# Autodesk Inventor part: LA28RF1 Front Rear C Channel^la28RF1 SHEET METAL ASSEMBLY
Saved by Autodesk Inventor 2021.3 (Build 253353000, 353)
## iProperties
Created: 2023-01
Part Number: LA28RF1 Front Rear C Channel^la28RF1 SHEET METAL ASSEMBLY
Material: Generic
Document SubType Name: Modeling
Designer: AdminForWorker
Density: 1 g/cm^3
Appearance: Default
Title: LA28RF1 Front Rear C Channel^la28RF1 SHEET METAL ASSEMBLY
Author: AdminForWorker
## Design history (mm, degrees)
feature "Cut-Extrude3"
body "Solid1"
